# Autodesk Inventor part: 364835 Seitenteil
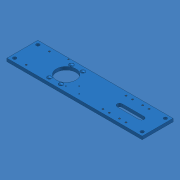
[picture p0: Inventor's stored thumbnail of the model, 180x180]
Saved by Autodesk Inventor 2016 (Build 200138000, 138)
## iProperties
Company: Mayer & Müller AG Schaltgeräte
Created: 2017-05
Part Number: 364835 Seitenteil
Material: 1.0120
Document SubType Name: Modeling
Designer: I.Baliuc
Manufacturer: Standard
Standards Organization: Custom
Description: Seitenteil, Trenner
Cost Center: 5,196 kg
Authority: 661896 mm^3
Density: 7.85 g/cm^3
Appearance: RAL 5012 Lichtblau
HalbzeugNorm: DIN 174
Zweck: HSLT / HSE - Standardseite
Abmessung: Fl. 120x12-170
SaveDate: 2006-10-28
SaveTime: 20:23
TotalMass: 5,196 kg
TotalVolume: 661896 mm^3
Kopiert_von_Autor: CH
Kopie_erstellt_am: 2017-05-01T12:47:30
Kopiert_von_Datei: D:\Inventor-Tools Tutorial\Bauteile\3\35\359999 Seitenteil.ipt
Kopie_Zieldatei: D:\Inventor-Tools Tutorial\Bauteile\3\36\364835 Seitenteil.ipt
Author: CH
Keywords: 380125
Revision Number: 364845
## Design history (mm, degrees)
sketch "Skizze2"
  geometry: L1 (-170, 60)-(355, 60); L2 (355, 60)-(355, -60); L3 (355, -60)-(-170, -60); L4 (-170, -60)-(-170, 60); L5 (-222.5, 0)-(512.5, 0) reference; L6 (0, -72)-(0, 96) reference; L7 (292.5, 10)-(207.5, 10); L8 (207.5, -10)-(292.5, -10); C1 r 38 at (0, 0); A1 r 10 centre (292.5, 0) between (292.5, -10) and (292.5, 10); A2 r 10 centre (207.5, 0) between (207.5, 10) and (207.5, -10)
  constraints: 12 end point, 4 point on circle, 4 point on line, 3 centre point, 3 parallel, 2 tangent, 1 horizontal, 1 perpendicular, 2 other
  dimensions: "d4" = 170 distance between parallel lines of L4 L6; "d5" = 525 distance of L1.start L1.end; "d6" = 120 distance of L3.end L1.start; "d7" = 76 diameter of C1; "d8" = 85 distance of A2.centre A1.centre; "d9" = 20 distance between parallel lines of L7 L8; "d10" = 62.5 distance from line of L2 A1.centre
extrude "Extrusion2" new body sketch "Skizze2" distance "d11" = 12; taper "d12" = 0 deg
sketch "Skizze3"
  geometry: L1 (355, 60)-(355, -60) reference; L2 (-170, -60)-(-170, 60) reference; L3 (-222.5, 0)-(512.5, 0) reference; 4 further points
  constraints: 2 symmetric about line
  dimensions: "d13" = 90 distance of point (-155, -45) point (-155, 45); "d14" = 15 distance from line of point (-155, 45) L2; "d15" = 90 distance of point (340, -45) point (340, 45) (= d13); "d16" = 15 distance from line of point (340, 45) L1 (= d14)
hole "Bohrung_Ø13" sketch "Skizze3" at (-155, 45), (-155, -45), (340, -45), (340, 45) diameter "d17" = 13; stored, may be unused: countersink angle "d21" = 90 deg, drill point angle "d23" = 118 deg; dims "d18" = 6, "d19" = 4, "d20" = 2, "d22" = 8
sketch "Skizze4"
  geometry: L1 (-222.5, 0)-(512.5, 0) reference; L2 (0, -72)-(0, 96) reference; 4 further points
  constraints: 3 symmetric about line
  dimensions: "d24" = 85 distance of point (22.5, -42.5) point (22.5, 42.5); "d25" = 45 distance of point (-22.5, 42.5) point (22.5, 42.5)
hole "Bohrung2" sketch "Skizze4" at (22.5, 42.5), (22.5, -42.5), (-22.5, -42.5), (-22.5, 42.5) diameter "d26" = 16.5; stored, may be unused: countersink angle "d30" = 90 deg, drill point angle "d32" = 0 deg; dims "d27" = 6, "d28" = 16.5, "d29" = 0.4, "d31" = 0.7
sketch "Skizze5"
  geometry: C1 r 8.25 at (0, 0) reference; C2 r 8.25 at (0, -85) reference; C3 r 8.25 at (45, -85) reference; C4 r 8.25 at (45, 0) reference; 4 further points
  constraints: 4 coincident
hole "Bohrung3" sketch "Skizze5" at (0, 0), (45, 0), (45, -85), (0, -85) diameter "d33" = 8.4; stored, may be unused: countersink angle "d37" = 90 deg, drill point angle "d39" = 118 deg; dims "d34" = 6, "d35" = 16.5 (= d26), "d36" = 2, "d38" = 8
sketch "Skizze6"
  geometry: L1 (-170, -60)-(-170, 60) reference; L2 (-222.5, 0)-(512.5, 0) reference; 2 further points
  constraints: 1 symmetric about line
  dimensions: "d40" = 90 distance of point (-110, -45) point (-110, 45); "d41" = 60 distance from line of point (-110, 45) L1
hole "Bohrung_M8_01" sketch "Skizze6" at (-110, 45), (-110, -45) diameter "d42" = 6.647; stored, may be unused: countersink angle "d46" = 90 deg, drill point angle "d48" = 118 deg; dims "d43" = 6, "d44" = 4, "d45" = 2, "d47" = 8
sketch "Skizze7"
  geometry: L1 (355, 60)-(355, -60) reference; L2 (-170, 60)-(355, 60) reference; L3 (-222.5, 0)-(512.5, 0) reference; 4 further points
  constraints: 1 horizontal, 1 vertical, 3 other
  dimensions: "d49" = 90 diameter of point (277, 45) L3; "d50" = 78 distance from line of L1 point (277, 45); "d53" = 90 distance of point (277, 45) point (277, -45) (= d49); "d56" = 25 distance of point (277, 45) point (252, 45)
hole "Bohrung_M8_02" sketch "Skizze7" at (277, 45), (277, -45), (252, 45), (252, -45) diameter "d59" = 6.647; stored, may be unused: countersink angle "d63" = 90 deg, drill point angle "d65" = 118 deg; dims "d60" = 6, "d61" = 4, "d62" = 2, "d64" = 8
hole "Bohrung_M6" diameter "d68" = 4.917; stored, may be unused: countersink angle "d72" = 90 deg, drill point angle "d74" = 118 deg; dims "d66" = 401, "d67" = 5, "d69" = 6, "d70" = 4, "d71" = 2, "d73" = 8
sketch "Skizze8"
  geometry: L1 (355, -60)-(-170, -60) reference; L2 (90.5, -40)-(38.5, -40); L3 (64.5, -14)-(64.5, -80.919); C1 r 38 at (0, 0) reference; 3 further points
  constraints: 4 end point, 3 coincident, 1 parallel, 1 perpendicular, 1 symmetric about line
  dimensions: "d75" = 26 distance from line of L3 point (38.5, -40); "d76" = 26 distance from line of L3 point (90.5, -40) (derived); "d77" = 26 distance from line of L2 point (64.5, -14); "d78" = 40 distance from line of L2 C1.centre; "d79" = 64.5 distance from line of L3 C1.centre
hole "Bohrung_M5" sketch "Skizze8" at (64.5, -14), (90.5, -40), (38.5, -40) diameter "d80" = 4.134; stored, may be unused: countersink angle "d84" = 90 deg, drill point angle "d86" = 118 deg; dims "d81" = 6, "d82" = 4, "d83" = 2, "d85" = 8
pattern_linear "Neue Bohrung (zusätzlich)" dims "d89" = 64.5
node "Center of Mass"
node "Volumenkörper1"
node "Volumenkörpern"
node "Oberflächenkörpern"
node "Projizierte Kontur1"
